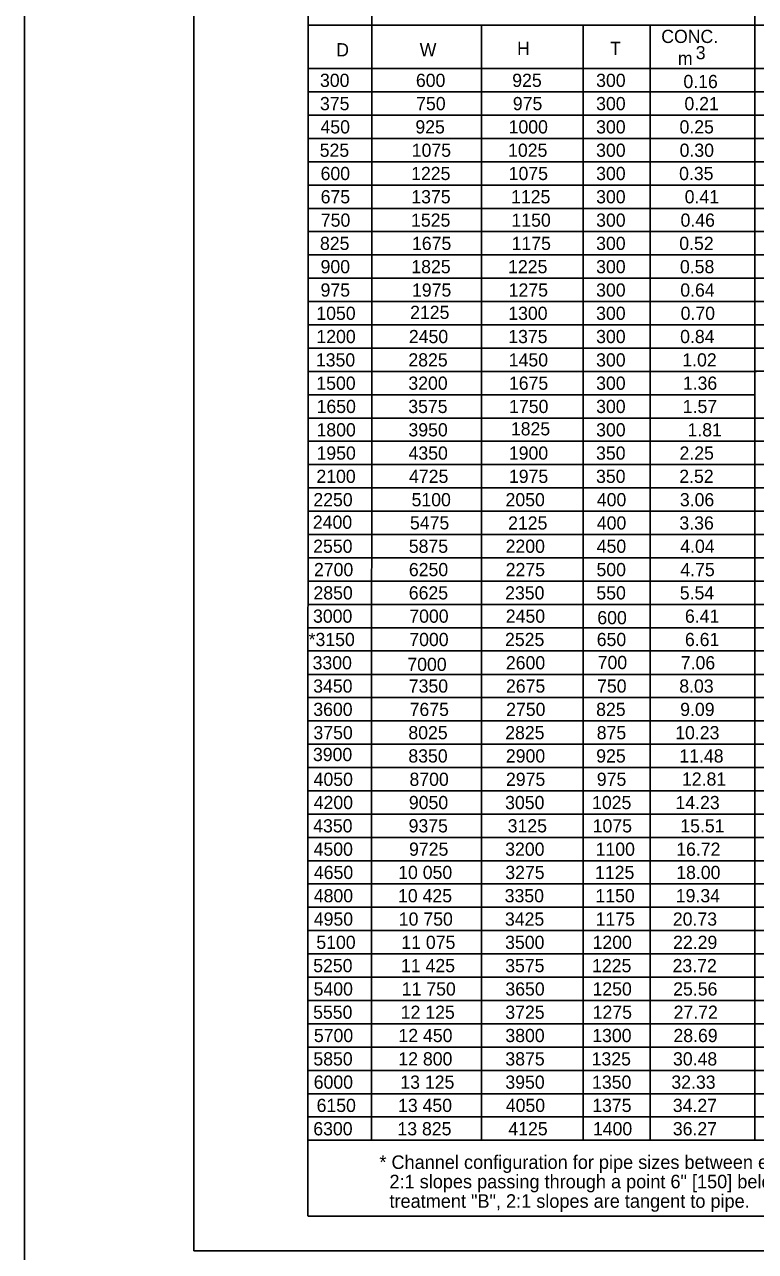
# Model space of a CAD drawing. Extents: x 1083.1 to 1117.1, y 675.4 to 741.4.
# Drawn here: x 1083.13 to 1091.76, y 697.84 to 712.34 of the extents above; entities that cross this region are included whole.
import ezdxf

# ---------------------------------------------------------------- set-up
doc = ezdxf.new("R2010")
doc.units = 0
doc.layers.add('Level 1', color=7, linetype='Continuous')

msp = doc.modelspace()

# ---------------------------------------------------------------- linework, layer by layer
at = {"layer": 'Level 1'}
for p, q in [((1086.478, 713.109), (1086.473, 698.26)), ((1087.228, 712.709), (1087.223, 699.159)), ((1091.754, 699.159), (1091.754, 712.709)), ((1103.658, 712.337), (1086.478, 712.337)), ((1088.525, 699.159), (1088.525, 712.337)), ((1089.725, 699.159), (1089.725, 712.337)), ((1090.518, 699.159), (1090.518, 712.337)), ((1103.658, 711.824), (1086.478, 711.824)), ((1103.658, 711.824), (1086.48, 711.824)), ((1103.658, 711.549), (1086.478, 711.549)), ((1103.658, 711.274), (1086.478, 711.274)), ((1103.658, 710.998), (1086.478, 710.998)), ((1103.658, 710.723), (1086.478, 710.723)), ((1103.658, 710.447), (1086.478, 710.447)), ((1103.658, 710.172), (1086.478, 710.172)), ((1103.658, 709.897), (1086.478, 709.897)), ((1103.658, 709.621), (1086.478, 709.621)), ((1103.658, 709.346), (1086.478, 709.346)), ((1097.691, 709.071), (1086.478, 709.071)), ((1097.691, 708.795), (1086.478, 708.795)), ((1103.658, 708.52), (1086.478, 708.52)), ((1091.771, 708.245), (1086.478, 708.245)), ((1091.756, 708.246), (1097.684, 708.246)), ((1091.758, 707.969), (1086.478, 707.969)), ((1091.751, 707.694), (1086.478, 707.694)), ((1091.75, 707.694), (1097.684, 707.694)), ((1103.658, 707.419), (1086.478, 707.419)), ((1103.658, 707.144), (1086.478, 707.144)), ((1103.658, 706.868), (1086.478, 706.868)), ((1103.658, 706.593), (1086.478, 706.593)), ((1103.658, 706.317), (1086.478, 706.317)), ((1103.658, 706.317), (1086.48, 706.317)), ((1103.658, 706.042), (1086.478, 706.042)), ((1103.658, 705.767), (1086.478, 705.767)), ((1103.658, 705.491), (1086.478, 705.491)), ((1103.658, 705.216), (1086.478, 705.216)), ((1103.658, 704.941), (1086.478, 704.941)), ((1103.658, 704.665), (1086.478, 704.665)), ((1103.658, 704.39), (1086.478, 704.39)), ((1103.658, 704.115), (1086.478, 704.115)), ((1103.658, 703.839), (1086.478, 703.839)), ((1103.658, 703.564), (1086.478, 703.564)), ((1103.658, 703.289), (1086.478, 703.289)), ((1103.658, 703.014), (1086.478, 703.014)), ((1103.658, 702.738), (1086.478, 702.738)), ((1103.658, 702.463), (1086.478, 702.463)), ((1103.658, 702.188), (1086.478, 702.188)), ((1103.658, 701.912), (1086.478, 701.912)), ((1103.658, 701.637), (1086.478, 701.637)), ((1103.658, 701.361), (1086.478, 701.361)), ((1103.658, 701.086), (1086.478, 701.086)), ((1103.658, 700.811), (1086.478, 700.811)), ((1103.658, 700.535), (1086.478, 700.535)), ((1103.658, 700.26), (1086.478, 700.26)), ((1103.658, 699.985), (1086.478, 699.985)), ((1103.658, 699.709), (1086.478, 699.709)), ((1103.658, 699.434), (1086.478, 699.434)), ((1087.69, 699.159), (1086.478, 699.159)), ((1103.658, 699.159), (1086.48, 699.159)), ((1103.658, 698.26), (1086.478, 698.26))]:
    msp.add_line(p, q, dxfattribs=at)
for points in [[(1083.126, 697.354), (1117.126, 697.354), (1117.126, 719.354), (1083.126, 719.354)], [(1083.126, 697.354), (1117.126, 697.354), (1117.126, 719.354), (1083.126, 719.354)], [(1085.126, 718.854), (1116.626, 718.854), (1116.626, 697.854), (1085.126, 697.854)]]:
    msp.add_lwpolyline(points, close=True, dxfattribs=at)

# ---------------------------------------------------------------- texts
for s, height, p in [('CONC.', 0.156, (1090.647, 712.126)), ('D', 0.156, (1086.808, 711.968)), ('W', 0.156, (1087.794, 711.968)), ('H', 0.156, (1088.944, 711.984)), ('T', 0.156, (1090.043, 711.984)), ('3', 0.156, (1091.055, 711.934)), ('m ', 0.156, (1090.844, 711.867)), ('300', 0.156, (1086.616, 711.607)), ('600', 0.156, (1087.749, 711.607)), ('925', 0.156, (1088.887, 711.607)), ('300', 0.156, (1089.878, 711.607)), ('0.16', 0.156, (1090.909, 711.593)), ('375', 0.156, (1086.616, 711.332)), ('750', 0.156, (1087.752, 711.332)), ('975', 0.156, (1088.894, 711.332)), ('300', 0.156, (1089.878, 711.332)), ('0.21', 0.156, (1090.921, 711.332)), ('450', 0.156, (1086.622, 711.057)), ('925', 0.156, (1087.743, 711.057)), ('1000', 0.156, (1088.844, 711.057)), ('300', 0.156, (1089.878, 711.057)), ('0.25', 0.156, (1090.863, 711.057)), ('525', 0.156, (1086.613, 710.781)), ('1075', 0.156, (1087.7, 710.781)), ('1025', 0.156, (1088.838, 710.781)), ('300', 0.156, (1089.878, 710.781)), ('0.30', 0.156, (1090.864, 710.781)), ('600', 0.156, (1086.623, 710.506)), ('1225', 0.156, (1087.693, 710.506)), ('1075', 0.156, (1088.845, 710.506)), ('300', 0.156, (1089.878, 710.506)), ('0.35', 0.156, (1090.858, 710.506)), ('675', 0.156, (1086.624, 710.231)), ('1375', 0.156, (1087.695, 710.231)), ('1125', 0.156, (1088.873, 710.231)), ('300', 0.156, (1089.878, 710.231)), ('0.41', 0.156, (1090.924, 710.231)), ('750', 0.156, (1086.626, 709.955)), ('1525', 0.156, (1087.692, 709.955)), ('1150', 0.156, (1088.878, 709.955)), ('300', 0.156, (1089.878, 709.955)), ('0.46', 0.156, (1090.875, 709.955)), ('825', 0.156, (1086.616, 709.68)), ('1675', 0.156, (1087.703, 709.68)), ('1175', 0.156, (1088.88, 709.68)), ('300', 0.156, (1089.878, 709.68)), ('0.52', 0.156, (1090.86, 709.68)), ('900', 0.156, (1086.623, 709.405)), ('1825', 0.156, (1087.695, 709.405)), ('1225', 0.156, (1088.838, 709.405)), ('300', 0.156, (1089.878, 709.405)), ('0.58', 0.156, (1090.868, 709.405)), ('975', 0.156, (1086.623, 709.129)), ('1975', 0.156, (1087.703, 709.129)), ('1275', 0.156, (1088.845, 709.129)), ('300', 0.156, (1089.878, 709.129)), ('0.64', 0.156, (1090.872, 709.129)), ('2125', 0.156, (1087.681, 708.865)), ('1050', 0.156, (1086.573, 708.854)), ('1300', 0.156, (1088.84, 708.854)), ('300', 0.156, (1089.878, 708.854)), ('0.70', 0.156, (1090.876, 708.854)), ('1200', 0.156, (1086.574, 708.579)), ('2450', 0.156, (1087.666, 708.579)), ('1375', 0.156, (1088.84, 708.579)), ('300', 0.156, (1089.878, 708.579)), ('0.84', 0.156, (1090.87, 708.579)), ('1350', 0.156, (1086.568, 708.303)), ('2825', 0.156, (1087.66, 708.303)), ('1450', 0.156, (1088.846, 708.303)), ('300', 0.156, (1089.878, 708.303)), ('1.02', 0.156, (1090.896, 708.303)), ('1500', 0.156, (1086.573, 708.028)), ('3200', 0.156, (1087.66, 708.028)), ('1675', 0.156, (1088.848, 708.028)), ('300', 0.156, (1089.878, 708.028)), ('1.36', 0.156, (1090.902, 708.028)), ('1650', 0.156, (1086.576, 707.753)), ('3575', 0.156, (1087.659, 707.753)), ('1750', 0.156, (1088.85, 707.753)), ('300', 0.156, (1089.878, 707.753)), ('1.57', 0.156, (1090.901, 707.753)), ('1800', 0.156, (1086.575, 707.477)), ('3950', 0.156, (1087.661, 707.477)), ('1825', 0.156, (1088.871, 707.489)), ('300', 0.156, (1089.878, 707.477)), ('1.81', 0.156, (1090.957, 707.477)), ('1950', 0.156, (1086.575, 707.202)), ('4350', 0.156, (1087.662, 707.202)), ('1900', 0.156, (1088.847, 707.202)), ('350', 0.156, (1089.877, 707.202)), ('2.25', 0.156, (1090.863, 707.202)), ('2100', 0.156, (1086.574, 706.927)), ('4725', 0.156, (1087.668, 706.927)), ('1975', 0.156, (1088.848, 706.927)), ('350', 0.156, (1089.877, 706.927)), ('2.52', 0.156, (1090.86, 706.927)), ('2250', 0.156, (1086.538, 706.651)), ('5100', 0.156, (1087.698, 706.651)), ('2050', 0.156, (1088.808, 706.651)), ('400', 0.156, (1089.886, 706.651)), ('3.06', 0.156, (1090.867, 706.651)), ('2400', 0.156, (1086.532, 706.385)), ('5475', 0.156, (1087.679, 706.378)), ('2125', 0.156, (1088.838, 706.376)), ('400', 0.156, (1089.886, 706.376)), ('3.36', 0.156, (1090.862, 706.376)), ('2550', 0.156, (1086.536, 706.101)), ('5875', 0.156, (1087.665, 706.101)), ('2200', 0.156, (1088.809, 706.101)), ('450', 0.156, (1089.885, 706.101)), ('4.04', 0.156, (1090.872, 706.101)), ('2700', 0.156, (1086.545, 705.825)), ('6250', 0.156, (1087.666, 705.825)), ('2275', 0.156, (1088.81, 705.825)), ('500', 0.156, (1089.882, 705.825)), ('4.75', 0.156, (1090.873, 705.825)), ('2850', 0.156, (1086.539, 705.55)), ('6625', 0.156, (1087.665, 705.55)), ('2350', 0.156, (1088.803, 705.55)), ('550', 0.156, (1089.881, 705.55)), ('5.54', 0.156, (1090.866, 705.55)), ('3000', 0.156, (1086.534, 705.275)), ('7000', 0.156, (1087.671, 705.275)), ('2450', 0.156, (1088.811, 705.275)), ('600', 0.156, (1089.892, 705.257)), ('6.41', 0.156, (1090.927, 705.275)), ('*3150', 0.156, (1086.482, 704.999)), ('7000', 0.156, (1087.671, 704.999)), ('2525', 0.156, (1088.802, 704.999)), ('650', 0.156, (1089.885, 704.999)), ('6.61', 0.156, (1090.927, 704.999)), ('3300', 0.156, (1086.529, 704.724)), ('7000', 0.156, (1087.648, 704.705)), ('2600', 0.156, (1088.812, 704.724)), ('700', 0.156, (1089.896, 704.727)), ('7.06', 0.156, (1090.878, 704.724)), ('3450', 0.156, (1086.536, 704.449)), ('7350', 0.156, (1087.665, 704.449)), ('2675', 0.156, (1088.813, 704.449)), ('750', 0.156, (1089.889, 704.449)), ('8.03', 0.156, (1090.86, 704.449)), ('3600', 0.156, (1086.537, 704.173)), ('7675', 0.156, (1087.675, 704.173)), ('2750', 0.156, (1088.815, 704.173)), ('825', 0.156, (1089.878, 704.173)), ('9.09', 0.156, (1090.871, 704.173)), ('3750', 0.156, (1086.539, 703.898)), ('8025', 0.156, (1087.66, 703.898)), ('2825', 0.156, (1088.804, 703.898)), ('875', 0.156, (1089.885, 703.898)), ('10.23', 0.156, (1090.812, 703.898)), ('3900', 0.156, (1086.533, 703.64)), ('8350', 0.156, (1087.66, 703.623)), ('2900', 0.156, (1088.812, 703.623)), ('925', 0.156, (1089.879, 703.623)), ('11.48', 0.156, (1090.861, 703.623)), ('12.81', 0.156, (1090.892, 703.35)), ('4050', 0.156, (1086.541, 703.347)), ('8700', 0.156, (1087.673, 703.347)), ('2975', 0.156, (1088.813, 703.347)), ('975', 0.156, (1089.886, 703.347)), ('4200', 0.156, (1086.542, 703.072)), ('9050', 0.156, (1087.666, 703.072)), ('3050', 0.156, (1088.803, 703.072)), ('1025', 0.156, (1089.83, 703.072)), ('14.23', 0.156, (1090.815, 703.072)), ('4350', 0.156, (1086.536, 702.797)), ('9375', 0.156, (1087.663, 702.797)), ('3125', 0.156, (1088.833, 702.797)), ('1075', 0.156, (1089.837, 702.797)), ('15.51', 0.156, (1090.872, 702.797)), ('4500', 0.156, (1086.541, 702.521)), ('9725', 0.156, (1087.668, 702.521)), ('3200', 0.156, (1088.804, 702.521)), ('1100', 0.156, (1089.872, 702.521)), ('16.72', 0.156, (1090.824, 702.521)), ('4650', 0.156, (1086.544, 702.246)), ('10 050', 0.156, (1087.54, 702.246)), ('3275', 0.156, (1088.805, 702.246)), ('1125', 0.156, (1089.865, 702.246)), ('18.00', 0.156, (1090.824, 702.246)), ('4800', 0.156, (1086.543, 701.971)), ('10 425', 0.156, (1087.538, 701.971)), ('3350', 0.156, (1088.798, 701.971)), ('1150', 0.156, (1089.87, 701.971)), ('19.34', 0.156, (1090.819, 701.971)), ('4950', 0.156, (1086.543, 701.695)), ('10 750', 0.156, (1087.547, 701.695)), ('3425', 0.156, (1088.801, 701.695)), ('1175', 0.156, (1089.872, 701.695)), ('20.73', 0.156, (1090.784, 701.695)), ('5100', 0.156, (1086.573, 701.42)), ('11 075', 0.156, (1087.577, 701.42)), ('3500', 0.156, (1088.803, 701.42)), ('1200', 0.156, (1089.836, 701.42)), ('22.29', 0.156, (1090.787, 701.42)), ('5250', 0.156, (1086.536, 701.145)), ('11 425', 0.156, (1087.573, 701.145)), ('3575', 0.156, (1088.804, 701.145)), ('1225', 0.156, (1089.83, 701.145)), ('23.72', 0.156, (1090.781, 701.145)), ('5400', 0.156, (1086.541, 700.869)), ('11 750', 0.156, (1087.582, 700.869)), ('3650', 0.156, (1088.806, 700.869)), ('1250', 0.156, (1089.835, 700.869)), ('25.56', 0.156, (1090.788, 700.869)), ('5550', 0.156, (1086.535, 700.594)), ('12 125', 0.156, (1087.57, 700.594)), ('3725', 0.156, (1088.805, 700.594)), ('1275', 0.156, (1089.837, 700.594)), ('27.72', 0.156, (1090.793, 700.594)), ('5700', 0.156, (1086.544, 700.319)), ('12 450', 0.156, (1087.543, 700.319)), ('3800', 0.156, (1088.806, 700.319)), ('1300', 0.156, (1089.832, 700.319)), ('28.69', 0.156, (1090.791, 700.319)), ('5850', 0.156, (1086.538, 700.043)), ('12 800', 0.156, (1087.542, 700.043)), ('3875', 0.156, (1088.806, 700.043)), ('1325', 0.156, (1089.825, 700.043)), ('30.48', 0.156, (1090.786, 700.043)), ('6000', 0.156, (1086.542, 699.768)), ('13 125', 0.156, (1087.565, 699.768)), ('3950', 0.156, (1088.806, 699.768)), ('1350', 0.156, (1089.83, 699.768)), ('32.33', 0.156, (1090.767, 699.768)), ('6150', 0.156, (1086.576, 699.493)), ('13 450', 0.156, (1087.538, 699.493)), ('4050', 0.156, (1088.811, 699.493)), ('1375', 0.156, (1089.832, 699.493)), ('34.27', 0.156, (1090.784, 699.493)), ('6300', 0.156, (1086.537, 699.217)), ('13 825', 0.156, (1087.531, 699.217)), ('4125', 0.156, (1088.841, 699.217)), ('1400', 0.156, (1089.84, 699.217)), ('36.27', 0.156, (1090.784, 699.217)), ('* Channel configuration for pipe sizes between end treatment "A" and end treatment "B" is determined by', 0.16, (1087.318, 698.82)), ('  2:1 slopes passing through a point 6" [150] below the top and at each side of the headwall.  For end', 0.16, (1087.318, 698.591)), ('  treatment "B", 2:1 slopes are tangent to pipe.', 0.16, (1087.318, 698.361))]:
    msp.add_text(s, height=height, dxfattribs=at).set_placement(p)

doc.saveas('drawing.dxf')
